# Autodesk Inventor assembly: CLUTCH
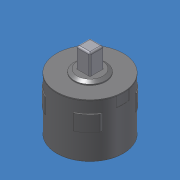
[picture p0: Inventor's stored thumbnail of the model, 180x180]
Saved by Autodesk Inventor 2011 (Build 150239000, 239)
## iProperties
Created: 2007-08
Part Number: CLUTCH
Document SubType Name: Assembly
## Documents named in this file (3)
- C:\Data Folder\VEX 2011\Inventor Datasets\Unit 7\Components\CLUTCH.iam
- C:\Data Folder\VEX 2011\Inventor Datasets\Unit 7\Components\Clutch Body.ipt
- C:\Data Folder\VEX 2011\Inventor Datasets\Unit 7\Components\Clutch Axle.ipt
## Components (2 placed, 2 different names)
1. Clutch Body:1 — Mate:1, Mate:2, Mate:3
2. Clutch Axle:1 — Mate:1, Mate:2, Mate:3
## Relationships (3: Mate 3)
- Mate:1: Clutch Body:1 ↔ Clutch Axle:1
- Mate:2: Clutch Body:1 ↔ Clutch Axle:1
- Mate:3: Clutch Body:1 ↔ Clutch Axle:1
